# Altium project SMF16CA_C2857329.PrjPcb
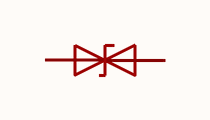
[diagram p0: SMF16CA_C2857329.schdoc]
1 sheet, 1 parts. Net scope: global (net labels, ports and power ports of the same name join across sheets).

## Sheet SMF16CA_C2857329.schdoc
size 127 x 101 mm

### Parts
D?  smf16ca_c2857329  [SOD-123FL_L2.8-W1.8-LS3.7-BI]  (value not drawn)

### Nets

Not connected (* = marked no-connect by the designer): D? 1(K) 2(A)

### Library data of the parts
D? = smf16ca_c2857329: 极性:双向;反向截止电压(Vrwm):16V;钳位电压:26V;峰值脉冲电流(Ipp):7.7A;峰值脉冲功率(Ppp):200W@10/1000us;击穿电压(VBR):17.8V;; Manufacturer: JSMSEMI(杰盛微); AddInBom: yes; ModelId: d105299b3871451c86f679efef28ff8f; ModelTransform: 145.669,70.866,0,0,0,0,0,0,0; Polarity: 双向; Reverse Stand-Off Voltage (Vrwm): 16V; Clamping Voltage: 26V; Peak Pulse Current (Ipp): 7.7A; Voltage - Breakdown: 17.8V; Reverse Leakage Current (Ir): 1uA; Number of Channels: 单路; Type: TVS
